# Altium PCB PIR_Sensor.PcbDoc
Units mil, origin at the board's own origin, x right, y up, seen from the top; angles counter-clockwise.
Board outline 800 x 700 mil, 4 copper layers (Top Layer, Ground Plane, Power Plane, Bottom Layer), stack 79.834 mil thick; 4 components, 3 nets, 11 pads, 2 vias.
Unrouted connection lines stored in the file: 1.
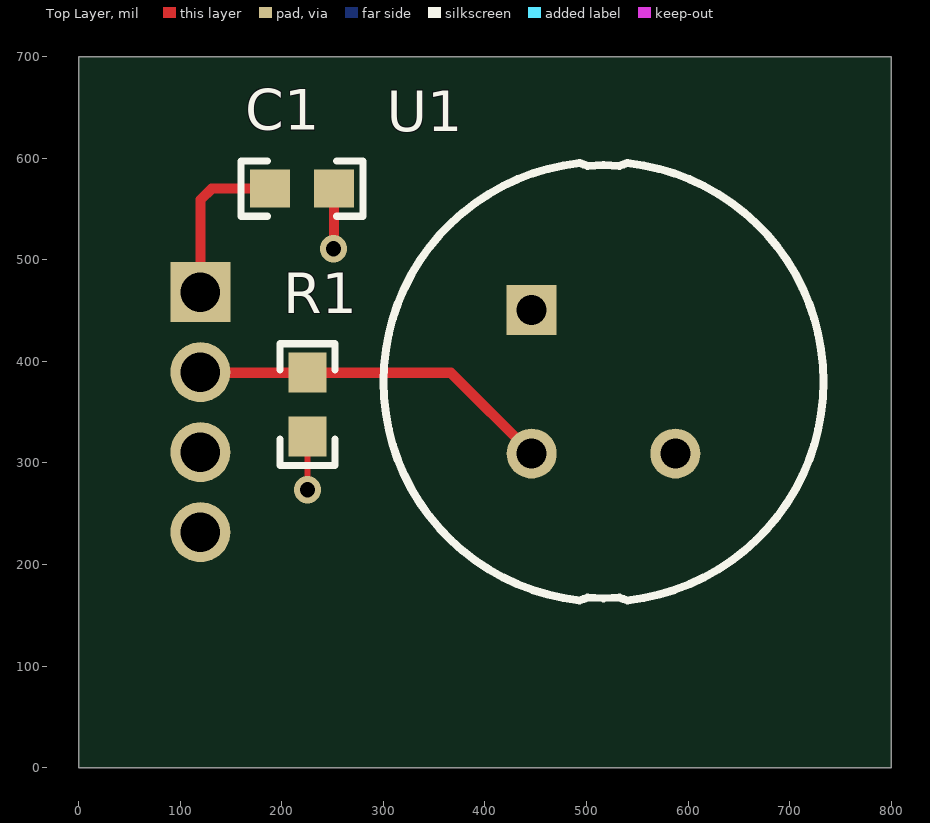
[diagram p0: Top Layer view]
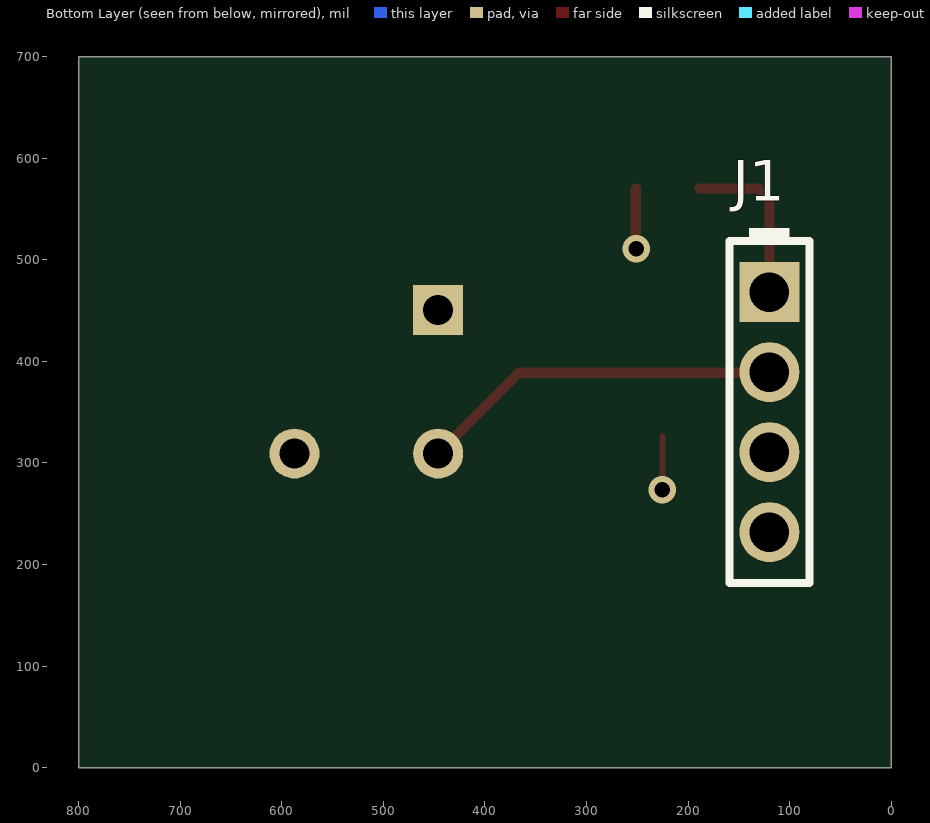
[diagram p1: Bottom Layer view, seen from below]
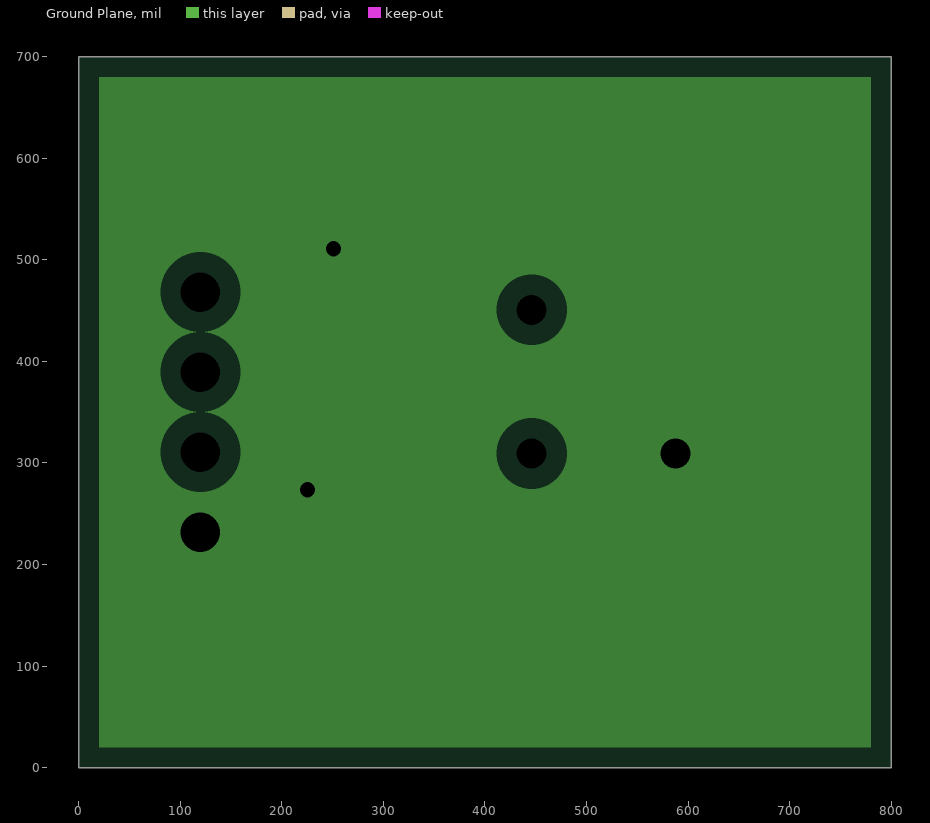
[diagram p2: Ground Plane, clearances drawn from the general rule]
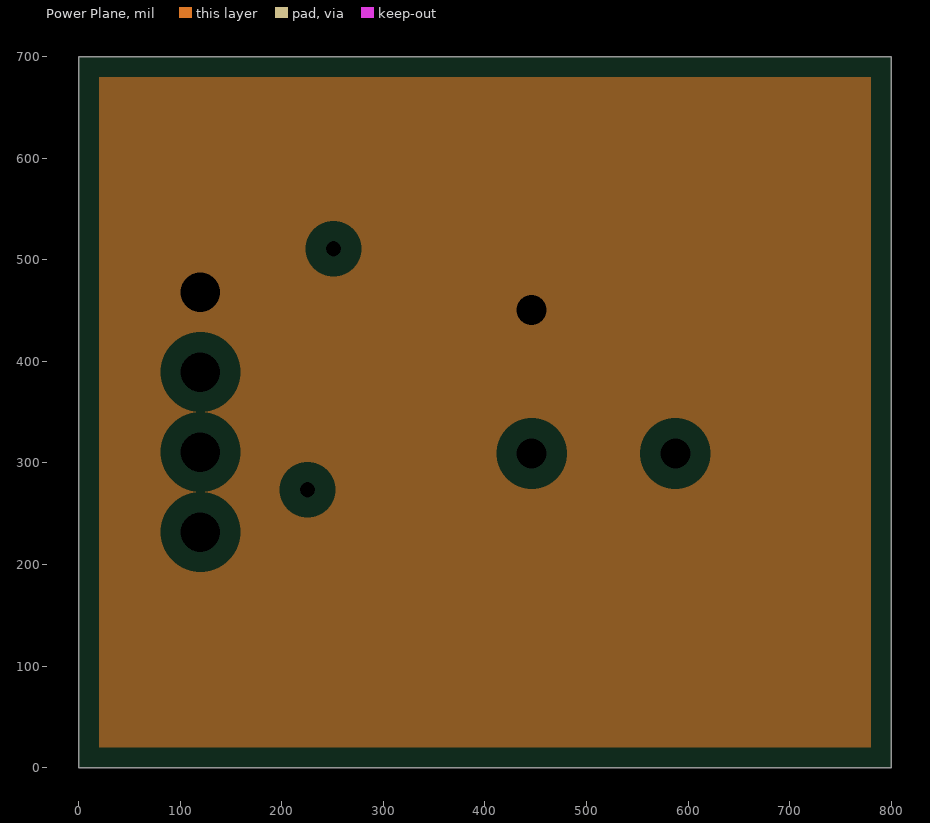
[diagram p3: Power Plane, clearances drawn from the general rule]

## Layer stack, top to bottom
Top Solder: solder mask 0.4, Solder Resist, Dk 3.5
Top Layer: signal copper 1.4
Dielectric1: core 59.2, FR-4, Dk 4.8
Ground Plane: plane copper 1.417, net GND
Dielectric 3: prepreg 5, Dk 4.2
Power Plane: plane copper 1.417, net VCC_3P3
Dielectric 2: core 10, Dk 4.2
Bottom Layer: signal copper 1.4
Bottom Solder: solder mask 0.4, Solder Resist, Dk 3.5

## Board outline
0,0 800,0 800,700 0,700

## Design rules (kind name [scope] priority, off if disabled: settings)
AcuteAngle [All] p1: minimum=4.50000000000000E+0001 checktracksonly=FALSE
AssemblyTestPointUsage [All] p1: valid=2
BoardOutlineClearance BoardOutlineClearance_MountingHoles [OnCopper and InComponentClass('Mounting Holes')] p1: gap=40
BoardOutlineClearance BoardOutlineClearance_Poly [OnCopper and IsPoly] p2: gap=25
BoardOutlineClearance [OnCopper and Not InComponentClass('Logo') and not InComponentClass('FiducialMark') and not InRegion(1000,500,4000,800) and not InPoly] p3: gap=75
Clearance Clearance_Keepouts [((IsTrack Or IsArc) And Not InPoly) And IsFree and IsKeepOut vs ((IsTrack Or IsArc) And Not InPoly) And IsFree and IsKeepOut] p1: gap=0
Clearance Clearance_Poly [InPolygon] p2: gap=25
Clearance [All] p3: gap=6
ComponentClearance ComponentClearance_MountingHoles_FiducialMarks [InComponentClass('Mounting Holes') vs InComponentClass('FiducialMark')] p1: gap=50 collisioncheckmode=3 verticalgap=10 showdistances=FALSE
ComponentClearance ComponentClearance_Shunt [InComponentClass('Header') vs InComponentClass('Shunt')] p2: gap=0 collisioncheckmode=3 verticalgap=0 showdistances=FALSE
ComponentClearance ComponentClearance_Logo [InComponentClass('Logo')] p3: gap=50 collisioncheckmode=3 verticalgap=10 showdistances=FALSE
ComponentClearance ComponentClearance_ScrewToNut [(HasFootprint('NY PMS 440 0025 PH')) vs (HasFootprint('Keystone_1902C'))] p4: gap=5 collisioncheckmode=3 verticalgap=10 showdistances=FALSE
ComponentClearance ComponentClearance_MountingHoles [InComponentClass('Mounting Holes')] p5: gap=250 collisioncheckmode=3 verticalgap=100000 showdistances=FALSE
ComponentClearance ComponentClearance_SmallPassives [HasFootprint('0201*') or HasFootprint('0402*') or HasFootprint('0508') or HasFootprint('0603*') or HasFootprint('0612') or HasFootprint('0805*') or HasFootprint('0815*') or HasFootprint('0830*') or HasFootprint('1206*') or HasFootprint('1210*') or HasFootprint('1808*') or HasFootprint('1812*') or HasFootprint('1825*') or HasFootprint('2010*') or HasFootprint('2220*') or HasFootprint('2225*') or HasFootprint('2512*') or HasFootprint('2728*') or HasFootprint('3518*') vs HasFootprint('0201*') or HasFootprint('0402*') or HasFootprint('0508') or HasFootprint('0603*') or HasFootprint('0612') or HasFootprint('0805*') or HasFootprint('0815*') or HasFootprint('0830*') or HasFootprint('1206*') or HasFootprint('1210*') or HasFootprint('1808*') or HasFootprint('1812*') or HasFootprint('1825*') or HasFootprint('2010*') or HasFootprint('2220*') or HasFootprint('2225*') or HasFootprint('2512*') or HasFootprint('2728*') or HasFootprint('3518*')] p6: gap=14.96 collisioncheckmode=3 verticalgap=10 showdistances=FALSE
ComponentClearance ComponentClearance_THtoSMT [IsThruComponent vs IsSMTComponent] p7: gap=40 collisioncheckmode=3 verticalgap=30 showdistances=FALSE
ComponentClearance ComponentClearance_THtoTH [IsThruComponent vs IsThruComponent] p8: gap=30 collisioncheckmode=3 verticalgap=30 showdistances=FALSE
ComponentClearance [All] p9: gap=30 collisioncheckmode=3 verticalgap=10 showdistances=FALSE
DiffPairsRouting [All] p1: maxlimit=100 minlimit=10 mostfreqgap=10 toplayer_minwidth=15 toplayer_maxwidth=15 toplayer_prefwidth=15 bottomlayer_minwidth=15 bottomlayer_maxwidth=15 bottomlayer_prefwidth=15 maxuncoupledlength=1000
FabricationTestPointUsage TestPointUsage [All] p1: valid=2 allowmultiple=FALSE
FabricationTestpoint Testpoint [All] p1: side=3 testpointundercomponent=TRUE minsize=40 maxsize=100 preferedsize=60 minholesize=0 maxholesize=40 preferedholesize=32 testpointgrid=1 allowsidetop=TRUE allowsidebottom=TRUE usegrid=TRUE gridtolerance=0.01
FanoutControl Fanout_LCC [IsLCC] p1: bgadir=Out bgaviamode=Centered fanoutstyle=Auto fanoutdirection=Alternating viagrid=1 // Fanout_LCC (Default Rule)
FanoutControl Fanout_BGA [IsBGA] p2: bgadir=Out bgaviamode=Centered fanoutstyle=Auto fanoutdirection=Alternating viagrid=1 // Fanout_BGA (Default Rule)
FanoutControl Fanout_Default [All] p4: bgadir=Out bgaviamode=Centered fanoutstyle=Auto fanoutdirection=Alternating viagrid=1 // Fanout_Default (Default Rule)
FanoutControl Fanout_Small [(CompPinCount < 5)] p5: bgadir=Out bgaviamode=Centered fanoutstyle=Auto fanoutdirection=OutThenIn viagrid=1 // Fanout_Small (Default Rule)
HoleSize [All] p1: absolutevalues=TRUE maxlimit=251 minlimit=7.87 maxpercent=80.000 minpercent=20.000
MinimumAnnularRing MinimumAnnularRing_ThermalPadVias [IsVia and InAnyComponent] p1: minimumring=5.91
MinimumAnnularRing [All] p2: minimumring=5
MinimumSolderMaskSliver MinimumSolderMaskSliver_Logo [InComponentClass('Logo') vs InComponentClass('Logo')] p1: minsoldermaskwidth=0.7
MinimumSolderMaskSliver [All] p2: minsoldermaskwidth=3.94
PlaneClearance [All] p1: clearance=20
PlaneConnect [All] p1: planeconnectstyle=Relief reliefexpansion=10 reliefentries=4 reliefconductorwidth=10 reliefairgap=10
PolygonConnect [All] p1: connectstyle=Relief reliefconductorwidth=10 reliefentries=4 polygonreliefangle="90 Angle" airgapwidth=10
RoutingVias ThermalPadVias [IsVia and InAnyComponent] p1: holewidth=7.87 width=19.68 viastyle="Through Hole" minholewidth=7.87 minwidth=19.68 maxholewidth=12.99 maxwidth=23.62
RoutingVias [All] p2: holewidth=15 width=27 viastyle="Through Hole" minholewidth=15 minwidth=27 maxholewidth=20 maxwidth=32
SilkToBoardRegionClearance [Not ((IsComment or IsDesignator) And (Hide <> 'False')) and not InRegion(1000,500,4000,800)] p1:
SilkToSilkClearance SilkToSilkClearance_Pb-FreeLogo [(HasFootprint('Pb-Free_Overlay_Medium') OR HasFootprint('Pb-Free_Overlay_Small')) vs (HasFootprint('Pb-Free_Overlay_Medium') OR HasFootprint('Pb-Free_Overlay_Small'))] p1: silktosilkclearance=0
SilkToSilkClearance [All] p2: silktosilkclearance=4
SilkToSolderMaskClearance SilkToComponentPadClearance [IsPad and InAnycomponent] p1: minsilkscreentomaskgap=5 clearancetoexposedcopper=TRUE
SilkToSolderMaskClearance "Silk to Solder Mask Opening" [All] p2: minsilkscreentomaskgap=4 clearancetoexposedcopper=FALSE
SolderMaskExpansion SolderMaskExpansion_1 [All] p1: expansion=-20
SolderMaskExpansion [All] p2: expansion=1.97
Width [All] p1: maxlimit=10 minlimit=6 preferedwidth=6 checkconnectedcopper=TRUE
14 further rules are at their usual default settings.

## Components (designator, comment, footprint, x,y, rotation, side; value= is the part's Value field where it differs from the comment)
C1 "GRM188R70J104KA01D" 0603 220,570 r0 top
J1 "SQT-104-01-L-S" Samtec-SQT-104-01-L-S 120,350 r270 bottom
R1 "CRCW0603220KJNEA" 0603 225.39,357.28 r90 top
U1 "EKMB1301111K" Panasonic_EKMB1301111K 516.73,379.92 r0 top

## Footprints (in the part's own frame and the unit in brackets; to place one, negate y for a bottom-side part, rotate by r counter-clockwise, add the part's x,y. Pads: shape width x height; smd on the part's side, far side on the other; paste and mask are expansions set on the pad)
0603 [mm] "0603 from SM-752 data"
  rect 1x0.95 smd: 1(-0.8,0) 2(0.8,0)
  silkscreen extent -1.52,-0.69 1.52,0.69, body extent -0.87,-0.47 0.87,0.47, height 1
Panasonic_EKMB1301111K [mm] "TH, 3-Leads, Dia 11mm"
  rect 1.25x1.25 hole 0.75: 1(-1.796,1.796)
  round 1.25 hole 0.75: 2(-1.796,-1.796) 3(1.796,-1.796)
  silkscreen extent -5.5,-5.47 5.5,5.47, body extent -5.5,-5.47 5.5,5.47, height 14.4
Samtec-SQT-104-01-L-S [mm] "TH, 4x1, Pitch 2mm"
  rect 1.5x1.5 hole 0.99: 1(-3,0)
  round 1.5 hole 0.99: 2(-1,0) 3(1,0) 4(3,0)
  silkscreen extent -4.6,-1 4.28,1, body extent -4.15,-1 4.15,1, height 6.35

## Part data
C1: "CAP, CERM, 0.1 µF, 6.3 V, +/- 10%, X7R, 0603"
J1: "Receptacle, 2mm, 4x1, Gold, TH"
R1: "RES, 220 k, 5%, 0.1 W, 0603"
U1: "High-sensitive human detection sensor with built-in amp, TH"

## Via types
v1: diameter 27, hole 15, Top Layer to Bottom Layer, 2 vias

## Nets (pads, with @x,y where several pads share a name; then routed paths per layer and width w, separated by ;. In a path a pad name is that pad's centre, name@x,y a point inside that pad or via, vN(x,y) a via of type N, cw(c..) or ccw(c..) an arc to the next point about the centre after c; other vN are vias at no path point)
GND: C1.2 J1.4 R1.1 U1.3 | length 111.6
  Top Layer w6: v1(225.39,273.62) R1.1
  Top Layer w10: v1(250.98,510.83) 251.5,511.34 C1.2
NetJ1_2: J1.2 R1.2 U1.2 | length 359.2
  Top Layer w10: J1.2 120.59,388.78 R1.2 366.45,388.78 U1.2
VCC_3P3: C1.1 J1.1 U1.1 | length 163.9
  Top Layer w10: J1.1 120,558.98 131.02,570 C1.1
pads on no net: J1.3

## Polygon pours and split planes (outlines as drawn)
GND on Ground Plane (split plane): 779.9,20.1 20.1,20.1 20.1,679.9 779.9,679.9
VCC_3P3 on Power Plane (split plane): 779.9,20.1 20.1,20.1 20.1,679.9 779.9,679.9

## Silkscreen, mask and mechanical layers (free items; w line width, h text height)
M1 Board Outline:
  the board outline again, w10
M2 Board Dimensions:
  rectangle: 125,-400 500,-275
  rectangle: 0,-275 125,-150
  lines w7: 0,-275 1000,-275 ; 125,-400 125,-150 ; 250,-400 250,-150 ; 500,-400 500,-150 ; 750,-400 750,-150 ; 0,-400 0,-150 1000,-150 1000,-400 0,-400
M5 Assembly Top:
  lines w10: -292,-930.17 6308,-930.17 ; -292,-726.83 6310,-726.83 ; -292,-523.5 -292,-1133.5 3713,-1133.5 6310,-1133.5 6310,-523.5 -291.5,-523.5 -291.5,-1133.5 1284,-1133.5 ; 2173,-1133.5 2173,-523.5 ; 3440,-726.83 3440,-523.5 ; 4280,-726.83 4280,-523.5 ; 4902,-1140 4902,-937.17
  text "COMPONENTS MARKED 'DNP' SHOULD NOT BE POPULATED." at 1153.5,-318.5 h60
  text "ASSEMBLY VARIANT:" at 1153,-434 h60
  text ".VariantName" at 2189,-434 h60
  text "PCB VIEWED FROM TOP SIDE" at -228.5,-655.67 h60
  text "BOARD #:" at 2248,-655.67 h60
  text ".PRJ_Number" at 2793.5,-655.67 h60
  text "REV:" at 3638,-655.67 h60
  text ".PCB_Rev" at 3929.5,-655.67 h60
  text "SVN REV:" at 4476,-655.67 h60
  text ".VersionControl_RevNumber" at 4982,-655.67 h60
  text "TID #:" at 2248,-859 h60
  text ".TID" at 2793.5,-859 h60
  text "PLOT NAME =" at -228.5,-1064.34 h60
  text ".plot_File_Name" at 577,-1064.34 h60
  text "GENERATED    :" at 2250,-1064.34 h60
  text ".Print_Date" at 3119.5,-1064.34 h60
  text ".Print_Time" at 3848.5,-1064.34 h60
  text "TEXAS INSTRUMENTS" at 5113,-1064.34 h60
M6 Assembly Bottom:
  lines w10: -292.5,-727.33 6309.5,-727.33 ; -290.5,-930.67 6309.5,-930.67 ; 1115.5,-1140.5 1115.5,-937.67 ; 1737.5,-727.33 1737.5,-524 ; 2577.5,-727.33 2577.5,-524 ; 3844.5,-1134 3844.5,-524 ; 4733.5,-1134 6309,-1134 6309,-524 -292.5,-524 -292.5,-1134 2304.5,-1134 6309.5,-1134 6309.5,-524
  text "COMPONENTS MARKED 'DNP' SHOULD NOT BE POPULATED." at 6102,-318 h60
  text ".VariantName" at 5058,-434 h60
  text "ASSEMBLY VARIANT:" at 6097,-434 h60
  text ".VersionControl_RevNumber" at 1035.5,-656.17 h60
  text "SVN REV:" at 1541.5,-656.17 h60
  text ".PCB_Rev" at 2088,-656.17 h60
  text "REV:" at 2379.5,-656.17 h60
  text ".PRJ_Number" at 3224,-656.17 h60
  text "BOARD #:" at 3769.5,-656.17 h60
  text "PCB VIEWED FROM BOTTOM SIDE" at 6246,-656.17 h60
  text ".TID" at 3224,-859.5 h60
  text "TID #:" at 3769.5,-859.5 h60
  text "TEXAS INSTRUMENTS" at 904.5,-1064.84 h60
  text ".Print_Time" at 2169,-1064.84 h60
  text ".Print_Date" at 2898,-1064.84 h60
  text "GENERATED    :" at 3767.5,-1064.84 h60
  text ".plot_File_Name" at 5440.5,-1064.84 h60
  text "PLOT NAME =" at 6246,-1064.84 h60
M9 Title Sheet:
  drawing of 57 lines, arcs and shapes, not listed
  text "1" at 739.84,8036.5 h70
  text "2" at 3235.5,8036.5 h70
  text "3" at 5724.84,8036.5 h70
  text "4" at 8231.51,8036.5 h70
  text "5" at 10730.5,8036.5 h70
  text "6" at 13235.5,8036.5 h70
  text "A" at -416.5,6893.5 h70
  text "A" at 14383.5,6893.5 h70
  text "B" at -416.5,4513.5 h70
  text "B" at 14383.5,4513.5 h70
  text "C" at -416.5,2138.5 h70
  text "C" at 14383.5,2138.5 h70
  text "PROJECT TITLE:" at 11343.5,277.5 h45
  text ".PRJ_Title" at 11393.5,144.17 h70
  text "DESIGNED FOR:" at 11343.5,-23.5 h45
  text ".PRJ_Customer" at 11393.5,-163.5 h70
  text "D" at -416.5,-231.5 h70
  text "D" at 14383.5,-231.5 h70
  text "FILE NAME:" at 11343.5,-323.5 h45
  text ".PCB_File_Name_No_Path" at 11393.5,-443.5 h70
  text "Texas Instruments (TI) and/or its licensors do not warrant the accuracy or completeness of this specification" at 6374,-605.34 h45
  text "ENGINEER:" at 11343.5,-613.5 h45
  text "LAYOUT BY:" at 12848.5,-613.5 h45
  text "or any information contained therein. TI and/or its licensors do not warrant that this design will meet" at 6329.01,-718 h45
  text ".PRJ_Engineer" at 11393.5,-768.49 h70
  text ".PCB_Layout" at 12899,-768.49 h70
  text "the specifications, will be suitable for your application or fit for any particular purpose, or will operate in" at 6329.01,-830.67 h45
  text ".Layer_Name" at 577,-858.49 h60
  text "ALTIUM DESIGNER VERSION:" at 12848.5,-923.5 h45
  text "an implementation. TI and/or its licensors do not warrant that the design is production worthy. You should" at 6329.01,-943.33 h45
  text "completely validate and test your design implementation to confirm the system functionality for your application." at 6374,-1056 h45
  text ".print_Scale" at 11393.5,-1056.83 h70
  text ".Application_BuildNumber" at 12899,-1056.83 h70
  text "1" at 739.84,-1263.5 h70
  text "2" at 3235.5,-1263.5 h70
  text "3" at 5724.84,-1263.5 h70
  text "4" at 8231.51,-1263.5 h70
  text "5" at 10730.5,-1263.5 h70
  text "6" at 13235.5,-1263.5 h70
M10 Fab Notes:
  drawing of 173 lines, arcs and shapes, not listed
  text "DESIGN INFORMATION" at 12378.02,6201 h60
  text "MIN. TRACK WIDTH:" at 11733.46,6021 h60
  text "8" at 12829.7,6021 h60
  text "MIL" at 12984.46,6021 h60
  text "MIN. CLEARANCE:" at 11733.46,5889 h60
  text "0.2" at 12769.7,5889 h60
  text "mm" at 12984.46,5889 h60
  text "MIN. VIA PAD SIZE:" at 11733.46,5757 h60
  text "24" at 12799.71,5757 h60
  text "MIL" at 12984.46,5757 h60
  text "0.05mm (2MIL)" at 12428.46,5615.29 h60
  text "MINIMUM ANNULAR RING" at 11404.23,5611 h60
  text "EXTERNAL" at 13136.46,5611 h60
  text "PER" at 11604.23,5493 h60
  text "IPC-D-275 CLASS 2 LEVEL C" at 11824.23,5493 h60
  text "MIL, HOLES" at 13312.46,5380.71 h60
  text "+/-" at 12920,5380 h60
  text "+/-" at 13774,5380 h60
  text "REGISTRATION TOLERANCES:" at 11404.23,5375 h60
  text "METAL" at 12604,5375 h60
  text "5" at 13180.2,5375 h60
  text "3" at 14013.2,5375 h60
  text "MIL" at 14129.46,5375 h60
  text "+/-" at 13774,5262 h60
  text "HOLE SIZE TOLERANCE (UNLESS OTHERWISE SPECIFIED):" at 11404.23,5257 h60
  text "3" at 14013.2,5257 h60
  text "MIL" at 14129.46,5257 h60
  text "MATERIAL:" at 11329.46,5047.54 h60
  text "FR-4 High Tg" at 12315.9,4907.21 h60
  text "FR-408" at 11750.46,4898.64 h60
  text "OTHER" at 13238.46,4898.64 h60
  text "X" at 12161,4895 h60
  text "62 MIL (1.6mm) +/-10%" at 12070.56,4735.92 h60
  text "THICKNESS:" at 11404.23,4731.64 h60
  text "X" at 11942.4,4731.64 h60
  text "OTHER" at 13355.46,4731.64 h60
  text "TOLERANCE:" at 11404.23,4573.64 h60
  text "X" at 12243.53,4573.64 h60
  text "ANSI IPC-6012 TYPE 3 CLASS 2" at 12430.48,4573.64 h60
  text "OTHER +/-" at 12430.46,4417.64 h60
  text "BOW & TWIST:" at 11404.23,4260.64 h60
  text "X" at 12243.53,4260.64 h60
  text "ANSI IPC-6012 TYPE 3 CLASS 2" at 12430.48,4260.64 h60
  text "OTHER +/-" at 12430.46,4102.13 h60
  text "DRILLING:" at 11329.46,3963.64 h60
  text "REFERENCE:" at 11404.23,3846.64 h60
  text "X" at 12052.46,3846.64 h60
  text "AS SHOWN" at 12239.46,3846.64 h60
  text "X" at 12953.46,3846.64 h60
  text "NC_DRILL FILES" at 13090.46,3846.64 h60
  text "PTH COPPER THICKNESS:" at 11404.23,3688.64 h60
  text "X" at 12534.46,3688.64 h60
  text "20-30 um" at 12671.46,3688.64 h60
  text "OTHER" at 13388.46,3688.64 h60
  text "BOARD FINISH:" at 11329.46,3529.64 h60
  text "SILKSCREEN:" at 11484.68,3411.64 h60
  text "X" at 12433.46,3411.64 h60
  text "TOP" at 12559.46,3411.64 h60
  text "X" at 12943.46,3411.64 h60
  text "BOTTOM" at 13070.46,3411.64 h60
  text "SILKSCREEN COLOR:" at 11484.68,3244.64 h60
  text "X" at 12432.42,3244.64 h60
  text "WHITE" at 12559.46,3244.64 h60
  text "OTHER" at 13070.46,3244.64 h60
  text "X" at 12563.42,3085.44 h60
  text "GREEN" at 12690.46,3085.44 h60
  text "OTHER" at 13308.46,3085.44 h60
  text "SOLDER RESIST COLOR:" at 11484.68,3074.64 h60
  text "X" at 12563.42,2915.44 h60
  text "MATTE" at 12690.46,2915.44 h60
  text "SEMI-GLOSS" at 13308,2914.8 h60
  text "IMMERSION GOLD (ENIG)" at 12390.46,2726.92 h60
  text "ENEPIG" at 13728,2723.64 h60
  text "SURFACE FINISH:" at 11329.46,2722.64 h60
  text "X" at 12203.51,2722.64 h60
  text "IMM. TIN/SILVER OR EQUIV" at 11659,2565.64 h60
  text "OTHER" at 13090.46,2565.64 h60
  text "ARRAY/PANEL:" at 11329.46,2386.64 h60
  text "CUT AND TRIM PER M1 BOARD OUTLINE" at 12390.46,2382.35 h60
  text "N.C. ROUTE" at 12390.46,2230.64 h60
  text "X" at 13069.46,2230.64 h60
  text "V. SCORE" at 13256.46,2230.64 h60
  text "CERTIFICATION:" at 11329.46,2093.64 h60
  text "MATERIALS AND WORKMANSHIP FOR ALL PCBS" at 12054.46,2093.64 h60
  text "TO MEET OR EXCEED THE REQUIREMENTS OF:" at 12054.46,1995.64 h60
  text "X" at 11680.96,1859.13 h60
  text "ANSI IPC-A-600F CLASS ->" at 11819.96,1859.13 h60
  text "X" at 13459.02,1859.13 h60
  text "2" at 13577.96,1859.14 h60
  text "1" at 13262.96,1857.64 h60
  text "3" at 13931.96,1857.64 h60
  text "X" at 12495.02,1699.64 h60
  text "RoHS" at 12631.96,1699.64 h60
  text "OTHER" at 13276.36,1699.64 h60
  text "PER ORDER" at 13673.42,1699.64 h60
  text "ALL BOARDS MUST MEET OR EXCEED UL94-V0 REQUIREMENTS." at 11357,1534 h60
  text "PCB MUST BEAR THE UL94V-0 UL REGISTERED MATERIAL ID NUMBER" at 11357,1414 h60
  text "ADDITIONAL REQUIREMENTS:" at 11329.46,1240.64 h60
  text "MICROSECTION:" at 11404.23,1125.64 h60
  text "YES" at 12309.96,1125.64 h60
  text "REQUIRED" at 13171.46,969.49 h60
  text "BARE BOARD ELEC. TEST:" at 11404.23,966.64 h60
  text "NONE" at 12709.96,966.64 h60
  text "X" at 13044.46,966.64 h60
  text "PER ORDER" at 13763.46,966.64 h60
M11 Gerber Information:
  lines w10: -292,-930.17 6308,-930.17 ; -292,-726.83 6310,-726.83 ; -292,-523.5 -292,-1133.5 3713,-1133.5 6310,-1133.5 6310,-523.5 -291.5,-523.5 -291.5,-1133.5 1284,-1133.5 ; 2173,-1133.5 2173,-523.5 ; 3440,-726.83 3440,-523.5 ; 4280,-726.83 4280,-523.5 ; 4902,-1140 4902,-937.17
  text "ALL ARTWORK VIEWED FROM TOP SIDE" at -228.5,-655.67 h60
  text "BOARD #:" at 2248,-655.67 h60
  text ".PRJ_Number" at 2793.5,-655.67 h60
  text "REV:" at 3638,-655.67 h60
  text ".PCB_Rev" at 3929.5,-655.67 h60
  text "SVN REV:" at 4476,-655.67 h60
  text ".VersionControl_RevNumber" at 4982,-655.67 h60
  text "LAYER NAME =" at -228.5,-858.49 h60
  text "TID #:" at 2248,-859 h60
  text ".TID" at 2793.5,-859 h60
  text "PLOT NAME =" at -228.5,-1064.34 h60
  text ".plot_File_Name" at 577,-1064.34 h60
  text "GENERATED    :" at 2250,-1064.34 h60
  text ".Print_Date" at 3119.5,-1064.34 h60
  text ".Print_Time" at 3848.5,-1064.34 h60
  text "TEXAS INSTRUMENTS" at 5113,-1064.34 h60
M12 Stackup:
  drawing of 191 lines, arcs and shapes, not listed
  text "Layer" at 9790.34,7830 h60
  text "Name" at 10200.26,7830 h60
  text "Material" at 11130,7830 h60
  text "Thickness" at 11989.77,7830 h60
  text "Constant" at 12639.6,7830 h60
  text "Board Layer Stack" at 13209.46,7830 h60
  text "1" at 9790.34,7710 h60
  text "Top Overlay" at 10200.26,7710 h60
  text "2" at 9790.34,7590 h60
  text "Top Solder" at 10200.26,7590 h60
  text "Solder Resist" at 11130,7590 h60
  text "0.40mil" at 11989.77,7590 h60
  text "3.5" at 12639.6,7590 h60
  text "3" at 9790.34,7470 h60
  text "Top Layer" at 10200.26,7470 h60
  text "Copper" at 11130,7470 h60
  text "1.40mil" at 11989.77,7470 h60
  text "4" at 9790.34,7350 h60
  text "Dielectric1" at 10200.26,7350 h60
  text "FR-4" at 11130,7350 h60
  text "59.20mil" at 11989.77,7350 h60
  text "4.8" at 12639.6,7350 h60
  text "5" at 9790.34,7230 h60
  text "Bottom Layer" at 10200.26,7230 h60
  text "Copper" at 11130,7230 h60
  text "1.40mil" at 11989.77,7230 h60
  text "6" at 9790.34,7110 h60
  text "Bottom Solder" at 10200.26,7110 h60
  text "Solder Resist" at 11130,7110 h60
  text "0.40mil" at 11989.77,7110 h60
  text "3.5" at 12639.6,7110 h60
  text "7" at 9790.34,6990 h60
  text "Bottom Overlay" at 10200.26,6990 h60
M14 Component Bodies Bottom:
  text ".Layer_Name" at 577,-858.49 h60
Mechanical 17:
  text ".Layer_Name" at 577,-858.49 h60
Mechanical 18:
  text ".Layer_Name" at 577,-858.49 h60
Mechanical 19:
  text ".Layer_Name" at 577,-858.49 h60

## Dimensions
0,0 to 800,0 on M2 Board Dimensions
0,0 to 0,700 on M2 Board Dimensions
0,-400 to 1000,-400 on M2 Board Dimensions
